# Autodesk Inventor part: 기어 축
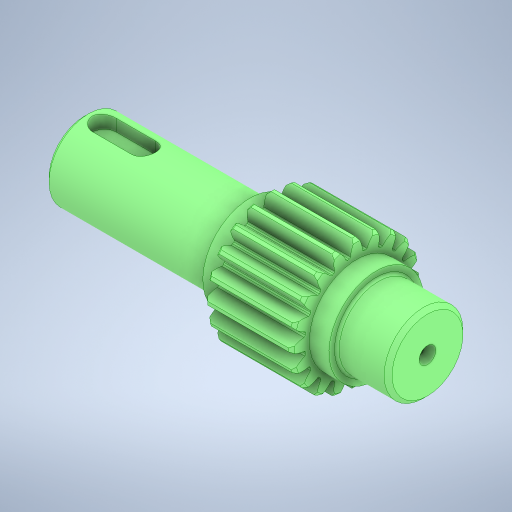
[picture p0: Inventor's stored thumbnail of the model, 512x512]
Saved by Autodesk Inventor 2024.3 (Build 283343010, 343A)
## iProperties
Created: 2025-11
Part Number: 기어 축
Material: 강철, 합금
Document SubType Name: Modeling
Designer: PC2-15
Density: 7.73 g/cm^3
Appearance: 기본값
Author: jhkim
Sending System: Autodesk Inventor 2026
Preprocessor: ST-DEVELOPER v20.1
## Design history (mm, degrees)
node "기어 축1"
node "솔리드2"
node "솔리드1"
